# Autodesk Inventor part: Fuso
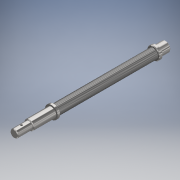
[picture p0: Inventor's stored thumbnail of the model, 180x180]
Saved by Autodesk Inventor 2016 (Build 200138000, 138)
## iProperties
Created: 2016-02
Part Number: Fuso
Material: Steel, High Strength, Low Alloy
Document SubType Name: Modeling
Designer: Vertex
Density: 7.85 g/cm^3
Appearance: Steel - Polished
Mass: 753.932 g
Surface Area: 206.303 cm^2
Volume: 96.0424 cm^3
Author: Vertex
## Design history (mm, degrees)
sketch "Sketch1"
  geometry: C1 r 10 at (0, 0); 1 further point
  constraints: 1 centre point, 1 coincident
  dimensions: "d0" = 20 diameter of C1
extrude "Extrusion1" new body sketch "Sketch1" distance "d1" = 20; taper "d2" = 0 deg
sketch "Sketch2"
  geometry: C1 r 13 at (0, 0); 1 further point
  constraints: 1 centre point, 1 coincident
  dimensions: "d3" = 26 diameter of C1
extrude "Extrusion2" join sketch "Sketch2" distance "d4" = 6; taper "d5" = 0 deg
sketch "Sketch3"
  geometry: C1 r 10 at (0, 0); 1 further point
  constraints: 1 centre point, 1 coincident
  dimensions: "d6" = 20 diameter of C1
extrude "Extrusion3" join sketch "Sketch3" distance "d7" = 201.4; taper "d8" = 0 deg
sketch "Sketch4"
  geometry: C1 r 13 at (0, 0); 1 further point
  constraints: 1 centre point, 1 coincident
  dimensions: "d9" = 26 diameter of C1
extrude "Extrusion4" join sketch "Sketch4" distance "d10" = 6; taper "d11" = 0 deg
sketch "Sketch5"
  geometry: C1 r 10 at (0, 0); 1 further point
  constraints: 1 centre point, 1 coincident
  dimensions: "d12" = 20 diameter of C1
extrude "Extrusion5" join sketch "Sketch5" distance "d13" = 46; taper "d14" = 0 deg
sketch "Sketch6"
  geometry: C1 r 8 at (0, 0); 1 further point
  constraints: 1 centre point, 1 coincident
  dimensions: "d15" = 16 diameter of C1
extrude "Extrusion6" join sketch "Sketch6" distance "d16" = 30; taper "d17" = 0 deg
workplane "Work Plane1"
sketch "Sketch7"
  geometry: L1 (10, 279.4)-(-10, 279.4) reference; L2 (8, 309.4)-(-8, 309.4) reference; C1 r 2.5 at (0, 294.4); 1 further point
  constraints: 1 centre point
  dimensions: "d20" = 15 distance from line of C1.centre L2; "d21" = 5 diameter of C1
chamfer "Chamfer1" distance "d22" = 1.25; stored, may be unused: second distance "d23" = 1.25, angle "d24" = 45 deg
hole "Hole1" sketch "Sketch7" diameter "d25" = 4.13; stored, may be unused: countersink angle "d29" = 90 deg, drill point angle "d31" = 118 deg; dims "d26" = 6, "d27" = 3.75, "d28" = 2.5, "d30" = 8
thread "Thread1" dims "d32" = 200, "d33" = 0
body "Solid1"
other parameters: "d18" = 8
